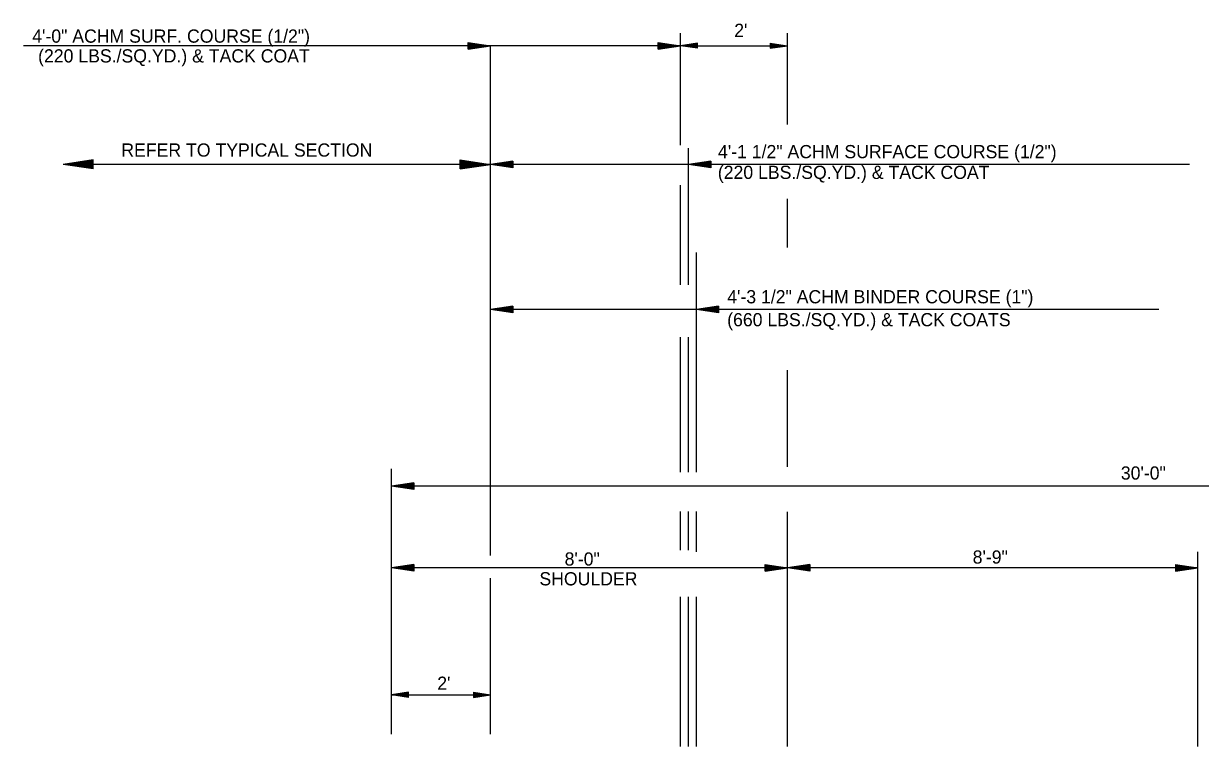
# Model space of a CAD drawing. Extents: x 634177 to 635904, y 289936 to 290970.
# Drawn here: x 635700.3 to 635753.8, y 290783.5 to 290816.4 of the extents above; entities that cross this region are included whole.
import ezdxf

# ---------------------------------------------------------------- set-up
doc = ezdxf.new("R2010")
doc.units = 0
doc.layers.add('Default', color=7, linetype='Continuous')

msp = doc.modelspace()

# ---------------------------------------------------------------- linework, layer by layer
at = {"layer": 'Default'}
for p, q in [((635730.136, 290810.868), (635730.136, 290815.959)), ((635734.996, 290811.798), (635734.996, 290815.959)), ((635730.496, 290815.386), (635700.272, 290815.386)), ((635720.484, 290815.537), (635721.496, 290815.386)), ((635720.484, 290815.234), (635720.484, 290815.537)), ((635720.484, 290815.512), (635721.327, 290815.386)), ((635720.484, 290815.487), (635721.153, 290815.386)), ((635720.484, 290815.461), (635720.984, 290815.386)), ((635720.484, 290815.435), (635720.813, 290815.386)), ((635720.484, 290815.41), (635720.644, 290815.386)), ((635720.484, 290815.234), (635721.496, 290815.386)), ((635720.484, 290815.337), (635720.813, 290815.386)), ((635720.484, 290815.284), (635721.153, 290815.386)), ((635720.484, 290815.259), (635721.327, 290815.386)), ((635720.484, 290815.311), (635720.984, 290815.386)), ((635720.484, 290815.361), (635720.644, 290815.386)), ((635721.496, 290792.223), (635721.496, 290815.386)), ((635729.123, 290815.537), (635730.136, 290815.386)), ((635729.123, 290815.234), (635729.123, 290815.537)), ((635729.123, 290815.512), (635729.967, 290815.386)), ((635729.123, 290815.487), (635729.793, 290815.386)), ((635729.123, 290815.461), (635729.624, 290815.386)), ((635729.123, 290815.435), (635729.453, 290815.386)), ((635729.123, 290815.41), (635729.283, 290815.386)), ((635729.123, 290815.234), (635730.136, 290815.386)), ((635729.123, 290815.337), (635729.453, 290815.386)), ((635729.123, 290815.284), (635729.793, 290815.386)), ((635729.123, 290815.259), (635729.967, 290815.386)), ((635729.123, 290815.311), (635729.624, 290815.386)), ((635729.123, 290815.361), (635729.283, 290815.386)), ((635730.912, 290815.502), (635730.136, 290815.386)), ((635730.912, 290815.269), (635730.136, 290815.386)), ((635730.912, 290815.483), (635730.266, 290815.386)), ((635730.912, 290815.289), (635730.266, 290815.386)), ((635730.912, 290815.463), (635730.399, 290815.386)), ((635730.912, 290815.308), (635730.399, 290815.386)), ((635730.496, 290815.386), (635734.996, 290815.386)), ((635730.912, 290815.443), (635730.528, 290815.386)), ((635730.912, 290815.328), (635730.528, 290815.386)), ((635730.912, 290815.424), (635730.66, 290815.386)), ((635730.912, 290815.348), (635730.66, 290815.386)), ((635730.912, 290815.404), (635730.79, 290815.386)), ((635730.912, 290815.367), (635730.79, 290815.386)), ((635730.912, 290815.269), (635730.912, 290815.502)), ((635734.22, 290815.502), (635734.996, 290815.386)), ((635734.22, 290815.502), (635734.22, 290815.269)), ((635734.22, 290815.483), (635734.866, 290815.386)), ((635734.22, 290815.463), (635734.733, 290815.386)), ((635734.22, 290815.443), (635734.604, 290815.386)), ((635734.22, 290815.423), (635734.472, 290815.386)), ((635734.22, 290815.404), (635734.342, 290815.386)), ((635734.22, 290815.269), (635734.996, 290815.386)), ((635734.22, 290815.348), (635734.472, 290815.386)), ((635734.22, 290815.308), (635734.733, 290815.386)), ((635734.22, 290815.289), (635734.866, 290815.386)), ((635734.22, 290815.328), (635734.604, 290815.386)), ((635734.22, 290815.367), (635734.342, 290815.386)), ((635730.496, 290810.488), (635730.496, 290810.731)), ((635703.434, 290810.196), (635702.066, 290809.991)), ((635721.496, 290809.991), (635702.066, 290809.991)), ((635703.434, 290809.785), (635702.066, 290809.991)), ((635703.434, 290810.16), (635702.293, 290809.991)), ((635703.434, 290809.819), (635702.293, 290809.991)), ((635703.434, 290810.126), (635702.527, 290809.991)), ((635703.434, 290809.853), (635702.527, 290809.991)), ((635703.434, 290810.093), (635702.754, 290809.991)), ((635703.434, 290809.888), (635702.754, 290809.991)), ((635703.434, 290810.056), (635702.987, 290809.991)), ((635703.434, 290809.925), (635702.987, 290809.991)), ((635703.434, 290810.022), (635703.217, 290809.991)), ((635703.434, 290809.956), (635703.217, 290809.991)), ((635703.434, 290809.785), (635703.434, 290810.196)), ((635753.281, 290809.991), (635716.996, 290809.991)), ((635720.126, 290810.195), (635721.496, 290809.991)), ((635720.126, 290809.785), (635720.126, 290810.195)), ((635720.126, 290810.162), (635721.269, 290809.991)), ((635720.126, 290810.126), (635721.032, 290809.991)), ((635720.126, 290810.093), (635720.803, 290809.991)), ((635720.126, 290810.056), (635720.572, 290809.991)), ((635720.126, 290810.023), (635720.344, 290809.991)), ((635720.126, 290809.785), (635721.496, 290809.991)), ((635720.126, 290809.922), (635720.572, 290809.991)), ((635720.126, 290809.853), (635721.032, 290809.991)), ((635720.126, 290809.819), (635721.269, 290809.991)), ((635720.126, 290809.889), (635720.803, 290809.991)), ((635720.126, 290809.958), (635720.344, 290809.991)), ((635722.509, 290810.143), (635721.496, 290809.991)), ((635722.509, 290809.839), (635721.496, 290809.991)), ((635722.509, 290810.118), (635721.665, 290809.991)), ((635722.509, 290809.865), (635721.665, 290809.991)), ((635722.509, 290810.091), (635721.839, 290809.991)), ((635722.509, 290809.89), (635721.839, 290809.991)), ((635722.509, 290810.066), (635722.008, 290809.991)), ((635722.509, 290809.915), (635722.008, 290809.991)), ((635722.509, 290810.04), (635722.179, 290809.991)), ((635722.509, 290809.942), (635722.179, 290809.991)), ((635722.509, 290810.014), (635722.349, 290809.991)), ((635722.509, 290809.967), (635722.349, 290809.991)), ((635722.509, 290810.143), (635722.509, 290809.839)), ((635730.496, 290804.512), (635730.496, 290810.488)), ((635731.509, 290810.143), (635730.496, 290809.991)), ((635731.509, 290809.839), (635730.496, 290809.991)), ((635731.509, 290810.118), (635730.665, 290809.991)), ((635731.509, 290809.865), (635730.665, 290809.991)), ((635731.509, 290810.091), (635730.839, 290809.991)), ((635731.509, 290809.89), (635730.839, 290809.991)), ((635731.509, 290810.066), (635731.008, 290809.991)), ((635731.509, 290809.915), (635731.008, 290809.991)), ((635731.509, 290810.04), (635731.179, 290809.991)), ((635731.509, 290809.942), (635731.179, 290809.991)), ((635731.509, 290810.014), (635731.349, 290809.991)), ((635731.509, 290809.967), (635731.349, 290809.991)), ((635731.509, 290810.143), (635731.509, 290809.839)), ((635730.136, 290804.512), (635730.136, 290809.053)), ((635734.996, 290806.216), (635734.996, 290808.433)), ((635730.858, 290796.005), (635730.858, 290805.986)), ((635722.509, 290803.55), (635721.496, 290803.398)), ((635751.887, 290803.398), (635721.496, 290803.398)), ((635722.509, 290803.246), (635721.496, 290803.398)), ((635722.509, 290803.525), (635721.665, 290803.398)), ((635722.509, 290803.272), (635721.665, 290803.398)), ((635722.509, 290803.498), (635721.839, 290803.398)), ((635722.509, 290803.297), (635721.839, 290803.398)), ((635722.509, 290803.473), (635722.008, 290803.398)), ((635722.509, 290803.322), (635722.008, 290803.398)), ((635722.509, 290803.447), (635722.179, 290803.398)), ((635722.509, 290803.349), (635722.179, 290803.398)), ((635722.509, 290803.422), (635722.349, 290803.398)), ((635722.509, 290803.374), (635722.349, 290803.398)), ((635722.509, 290803.55), (635722.509, 290803.246)), ((635731.87, 290803.55), (635730.858, 290803.398)), ((635731.87, 290803.246), (635730.858, 290803.398)), ((635731.87, 290803.525), (635731.027, 290803.398)), ((635731.87, 290803.272), (635731.027, 290803.398)), ((635731.87, 290803.498), (635731.201, 290803.398)), ((635731.87, 290803.297), (635731.201, 290803.398)), ((635731.87, 290803.473), (635731.37, 290803.398)), ((635731.87, 290803.322), (635731.37, 290803.398)), ((635731.87, 290803.447), (635731.541, 290803.398)), ((635731.87, 290803.349), (635731.541, 290803.398)), ((635731.87, 290803.422), (635731.71, 290803.398)), ((635731.87, 290803.374), (635731.71, 290803.398)), ((635731.87, 290803.55), (635731.87, 290803.246)), ((635730.136, 290796.005), (635730.136, 290802.138)), ((635730.496, 290796.005), (635730.496, 290802.138)), ((635734.996, 290796.246), (635734.996, 290800.638)), ((635716.996, 290784.097), (635716.996, 290796.161)), ((635718.008, 290795.52), (635716.996, 290795.368)), ((635718.008, 290795.216), (635716.996, 290795.368)), ((635784.496, 290795.368), (635716.996, 290795.368)), ((635718.008, 290795.495), (635717.165, 290795.368)), ((635718.008, 290795.242), (635717.165, 290795.368)), ((635718.008, 290795.468), (635717.339, 290795.368)), ((635718.008, 290795.267), (635717.339, 290795.368)), ((635718.008, 290795.443), (635717.508, 290795.368)), ((635718.008, 290795.292), (635717.508, 290795.368)), ((635718.008, 290795.417), (635717.679, 290795.368)), ((635718.008, 290795.319), (635717.679, 290795.368)), ((635718.008, 290795.391), (635717.848, 290795.368)), ((635718.008, 290795.344), (635717.848, 290795.368)), ((635718.008, 290795.52), (635718.008, 290795.216)), ((635730.136, 290792.459), (635730.136, 290794.215)), ((635730.496, 290792.459), (635730.496, 290794.215)), ((635730.858, 290792.387), (635730.858, 290794.215)), ((635734.994, 290792.758), (635734.994, 290794.208)), ((635734.996, 290783.536), (635734.996, 290793.07)), ((635753.657, 290783.536), (635753.657, 290792.389)), ((635718.009, 290791.8), (635716.996, 290791.649)), ((635718.009, 290791.8), (635718.009, 290791.497)), ((635733.984, 290791.8), (635734.996, 290791.649)), ((635733.984, 290791.497), (635733.984, 290791.8)), ((635736.009, 290791.8), (635734.996, 290791.649)), ((635736.009, 290791.8), (635736.009, 290791.497)), ((635752.645, 290791.8), (635753.657, 290791.649)), ((635752.645, 290791.8), (635752.645, 290791.497)), ((635718.009, 290791.497), (635716.996, 290791.649)), ((635753.657, 290791.649), (635716.996, 290791.649)), ((635718.009, 290791.775), (635717.165, 290791.649)), ((635718.009, 290791.522), (635717.165, 290791.649)), ((635718.009, 290791.749), (635717.339, 290791.649)), ((635718.009, 290791.547), (635717.339, 290791.649)), ((635718.009, 290791.723), (635717.508, 290791.649)), ((635718.009, 290791.573), (635717.508, 290791.649)), ((635718.009, 290791.697), (635717.679, 290791.649)), ((635718.009, 290791.599), (635717.679, 290791.649)), ((635718.009, 290791.672), (635717.849, 290791.649)), ((635718.009, 290791.624), (635717.849, 290791.649)), ((635733.984, 290791.775), (635734.827, 290791.649)), ((635733.984, 290791.75), (635734.653, 290791.649)), ((635733.984, 290791.723), (635734.484, 290791.649)), ((635733.984, 290791.698), (635734.313, 290791.649)), ((635733.984, 290791.673), (635734.143, 290791.649)), ((635733.984, 290791.497), (635734.996, 290791.649)), ((635733.984, 290791.6), (635734.313, 290791.649)), ((635733.984, 290791.547), (635734.653, 290791.649)), ((635733.984, 290791.522), (635734.827, 290791.649)), ((635733.984, 290791.574), (635734.484, 290791.649)), ((635733.984, 290791.624), (635734.143, 290791.649)), ((635736.009, 290791.497), (635734.996, 290791.649)), ((635736.009, 290791.775), (635735.165, 290791.649)), ((635736.009, 290791.522), (635735.165, 290791.649)), ((635736.009, 290791.749), (635735.339, 290791.649)), ((635736.009, 290791.547), (635735.339, 290791.649)), ((635736.009, 290791.723), (635735.508, 290791.649)), ((635736.009, 290791.573), (635735.508, 290791.649)), ((635736.009, 290791.697), (635735.679, 290791.649)), ((635736.009, 290791.599), (635735.679, 290791.649)), ((635736.009, 290791.672), (635735.849, 290791.649)), ((635736.009, 290791.624), (635735.849, 290791.649)), ((635752.645, 290791.775), (635753.488, 290791.649)), ((635752.645, 290791.749), (635753.314, 290791.649)), ((635752.645, 290791.723), (635753.145, 290791.649)), ((635752.645, 290791.697), (635752.974, 290791.649)), ((635752.645, 290791.672), (635752.805, 290791.649)), ((635752.645, 290791.497), (635753.657, 290791.649)), ((635752.645, 290791.599), (635752.974, 290791.649)), ((635752.645, 290791.547), (635753.314, 290791.649)), ((635752.645, 290791.522), (635753.488, 290791.649)), ((635752.645, 290791.573), (635753.145, 290791.649)), ((635752.645, 290791.624), (635752.805, 290791.649)), ((635721.496, 290784.097), (635721.496, 290791.19)), ((635730.136, 290783.536), (635730.136, 290790.333)), ((635730.496, 290783.536), (635730.496, 290790.333)), ((635730.858, 290783.536), (635730.858, 290790.333)), ((635717.772, 290785.999), (635716.996, 290785.883)), ((635717.772, 290785.98), (635717.126, 290785.883)), ((635717.772, 290785.96), (635717.259, 290785.883)), ((635717.772, 290785.941), (635717.388, 290785.883)), ((635717.772, 290785.921), (635717.52, 290785.883)), ((635717.772, 290785.767), (635717.772, 290785.999)), ((635720.72, 290785.999), (635721.496, 290785.883)), ((635720.72, 290785.999), (635720.72, 290785.767)), ((635720.72, 290785.98), (635721.366, 290785.883)), ((635720.72, 290785.96), (635721.233, 290785.883)), ((635720.72, 290785.941), (635721.104, 290785.883)), ((635720.72, 290785.921), (635720.972, 290785.883)), ((635716.996, 290785.883), (635721.496, 290785.883)), ((635717.772, 290785.767), (635716.996, 290785.883)), ((635717.772, 290785.786), (635717.126, 290785.883)), ((635717.772, 290785.806), (635717.259, 290785.883)), ((635717.772, 290785.825), (635717.388, 290785.883)), ((635717.772, 290785.845), (635717.52, 290785.883)), ((635717.772, 290785.901), (635717.65, 290785.883)), ((635717.772, 290785.865), (635717.65, 290785.883)), ((635720.72, 290785.901), (635720.842, 290785.883)), ((635720.72, 290785.767), (635721.496, 290785.883)), ((635720.72, 290785.845), (635720.972, 290785.883)), ((635720.72, 290785.806), (635721.233, 290785.883)), ((635720.72, 290785.786), (635721.366, 290785.883)), ((635720.72, 290785.825), (635721.104, 290785.883)), ((635720.72, 290785.865), (635720.842, 290785.883))]:
    msp.add_line(p, q, dxfattribs=at)

# ---------------------------------------------------------------- texts
for s, p in [('4\'-0" ACHM SURF. COURSE (1/2")', (635700.667, 290815.524)), ("2'", (635732.579, 290815.785)), ('(220 LBS./SQ.YD.) & TACK COAT', (635700.934, 290814.624)), ('REFER TO TYPICAL SECTION', (635704.717, 290810.345)), ('4\'-1 1/2" ACHM SURFACE COURSE (1/2")', (635731.842, 290810.273)), ('(220 LBS./SQ.YD.) & TACK COAT', (635731.833, 290809.332)), ('4\'-3 1/2" ACHM BINDER COURSE (1")', (635732.261, 290803.677)), ('(660 LBS./SQ.YD.) & TACK COATS', (635732.258, 290802.634)), ('30\'-0"', (635750.154, 290795.666)), ('8\'-0"', (635724.869, 290791.757)), ('8\'-9"', (635743.419, 290791.847)), ('SHOULDER', (635723.723, 290790.857)), ("2'", (635719.079, 290786.111))]:
    msp.add_text(s, height=0.6, dxfattribs=at).set_placement(p)

doc.saveas('drawing.dxf')
